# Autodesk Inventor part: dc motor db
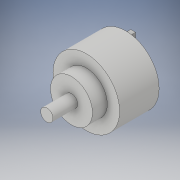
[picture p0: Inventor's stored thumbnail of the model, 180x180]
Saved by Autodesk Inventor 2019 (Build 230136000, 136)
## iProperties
Created: 2020-02
Part Number: dc motor db
Material: Generic
Document SubType Name: Modeling
Designer: user
Density: 1 g/cm^3
Appearance: Default
Author: user
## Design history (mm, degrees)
sketch "Sketch1"
  geometry: C1 r 67.5 at (0, 0); 1 further point
  constraints: 1 centre point, 1 coincident
  dimensions: "d0" = 135 diameter of C1
extrude "Extrusion1" new body sketch "Sketch1" distance "d1" = 80; taper "d2" = 0 deg
sketch "Sketch2"
  geometry: C1 r 42.5 at (0, 0); 1 further point
  constraints: 1 centre point, 1 coincident
  dimensions: "d3" = 85 diameter of C1
extrude "Extrusion2" join sketch "Sketch2" distance "d4" = 30; taper "d5" = 0 deg
sketch "Sketch3"
  geometry: C1 r 12.5 at (0, 0); 1 further point
  constraints: 1 centre point, 1 coincident
  dimensions: "d6" = 25 diameter of C1
extrude "Extrusion3" join sketch "Sketch3" distance "d7" = 50; taper "d8" = 0 deg
sketch "Sketch4"
  geometry: L1 (5, 60)-(-5, 60); L2 (-5, 60)-(-5, 50); L3 (-5, 50)-(5, 50); L4 (5, 50)-(5, 60); L5 (5, 60)-(-5, 50); L6 (-5, 60)-(5, 50); L7 (5, -50)-(-5, -50); L8 (-5, -50)-(-5, -60); L9 (-5, -60)-(5, -60); L10 (5, -60)-(5, -50); L11 (5, -50)-(-5, -60); L12 (-5, -50)-(5, -60); 5 further points
  constraints: 24 end point, 4 midpoint, 4 parallel, 2 horizontal, 2 perpendicular, 1 vertical alignment, 1 other
  dimensions: "d9" = 10 distance of L3.end L2.end; "d10" = 10 distance of L2.end L1.end; "d11" = 10 distance of L9.end L8.end; "d12" = 10 distance of L8.end L7.end; "d13" = 60 distance from line of point (0, 0) L1; "d14" = 60 distance from line of L9 point (0, 0)
extrude "Extrusion4" join sketch "Sketch4" distance "d15" = 15; taper "d16" = 0 deg
body "Solid1"
